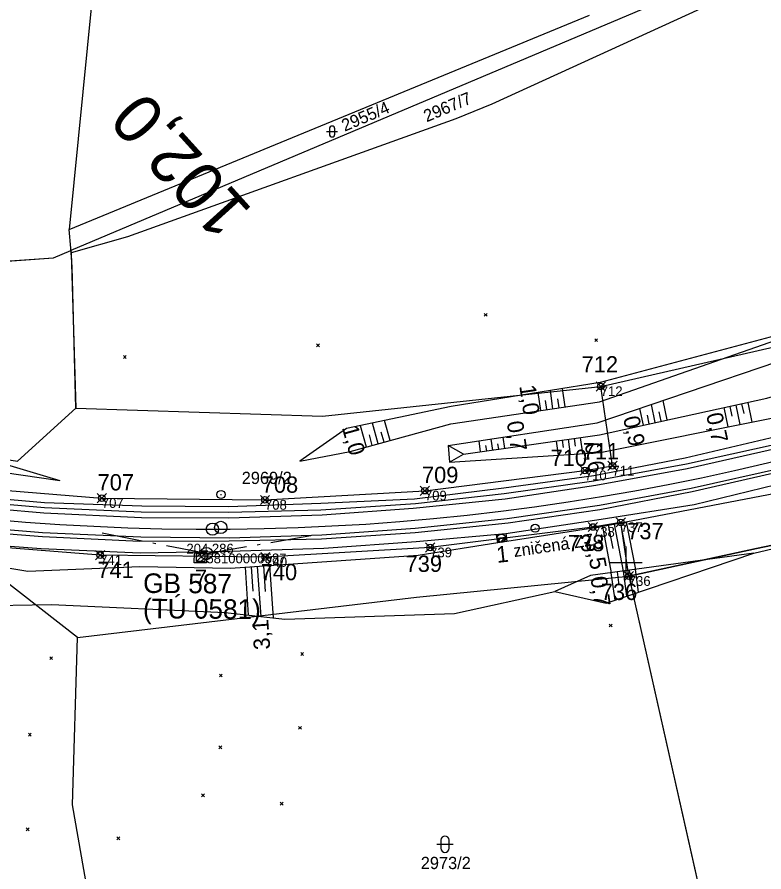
# Model space of a CAD drawing. Extents: x -800194 to -799078, y -1007177 to -1006597.
# Drawn here: x -799674.6 to -799583.1, y -1007037.9 to -1006933.1 of the extents above; entities that cross this region are included whole.
import ezdxf

# ---------------------------------------------------------------- set-up
doc = ezdxf.new("R2010")
doc.units = 0
for name, color, linetype in [('02_Osa_koleje', 7, 'Continuous'), ('_Vrstva 7 - Přesunutá', 7, 'Continuous'), ('Obvod stavby', 7, 'Continuous'), ('Ramove udaje', 7, 'Continuous'), ('Vrstva 11', 7, 'Continuous'), ('Vrstva 12', 7, 'Continuous'), ('Vrstva 4', 7, 'Continuous'), ('Vrstva 48', 7, 'Continuous'), ('Vrstva 49', 7, 'Continuous'), ('Vrstva 50', 7, 'Continuous'), ('Vrstva 53', 7, 'Continuous'), ('Vrstva 55', 7, 'Continuous'), ('Vrstva 57', 7, 'Continuous'), ('Vrstva 58', 7, 'Continuous'), ('Vrstva 60', 7, 'Continuous'), ('Vrstva 61', 7, 'Continuous'), ('Vrstva 63', 7, 'Continuous'), ('Vrstva 7', 7, 'Continuous')]:
    doc.layers.add(name, color=color, linetype=linetype)

msp = doc.modelspace()

# ---------------------------------------------------------------- linework, layer by layer
at = {"layer": '02_Osa_koleje'}
msp.add_arc((-799651.02, -1006703.89), 292, 255.6249, 308.2052, dxfattribs=at)
at = {"layer": '_Vrstva 7 - Přesunutá'}
msp.add_circle((-799650.67, -1006995.89), 0.75, dxfattribs=at)
at = {"layer": 'Obvod stavby'}
for p, q in [((-799603.64, -1006978.96), (-799602.5, -1006977.82)), ((-799603.64, -1006977.82), (-799602.5, -1006978.96)), ((-799605.58, -1006989.27), (-799604.45, -1006988.13)), ((-799605.58, -1006988.13), (-799604.45, -1006989.27)), ((-799602.19, -1006988.7), (-799601.06, -1006987.57)), ((-799602.19, -1006987.57), (-799601.06, -1006988.7)), ((-799625.19, -1006991.75), (-799624.06, -1006990.62)), ((-799625.19, -1006990.62), (-799624.06, -1006991.75)), ((-799664.79, -1006992.66), (-799663.66, -1006991.53)), ((-799664.79, -1006991.53), (-799663.66, -1006992.66)), ((-799644.79, -1006992.88), (-799643.66, -1006991.75)), ((-799644.79, -1006991.75), (-799643.66, -1006992.88)), ((-799601.17, -1006995.62), (-799600.04, -1006994.49)), ((-799601.17, -1006994.49), (-799600.04, -1006995.62)), ((-799604.59, -1006996.19), (-799603.45, -1006995.06)), ((-799604.59, -1006995.06), (-799603.45, -1006996.19)), ((-799624.55, -1006998.72), (-799623.42, -1006997.59)), ((-799624.55, -1006997.59), (-799623.42, -1006998.72)), ((-799664.99, -1006999.65), (-799663.86, -1006998.52)), ((-799664.99, -1006998.52), (-799663.86, -1006999.65)), ((-799644.75, -1006999.88), (-799643.62, -1006998.75)), ((-799644.75, -1006998.75), (-799643.62, -1006999.88)), ((-799600.2, -1007002.22), (-799599.06, -1007001.08)), ((-799600.2, -1007001.08), (-799599.06, -1007002.22))]:
    msp.add_line(p, q, dxfattribs=at)
for points in [[(-799683.81, -1006990.52), (-799664.23, -1006992.09), (-799644.23, -1006992.31), (-799624.62, -1006991.18), (-799605.02, -1006988.7), (-799601.63, -1006988.13), (-799603.07, -1006978.39), (-799559.64, -1006968.48), (-799519.68, -1006952.01)], [(-799521.98, -1006977.8), (-799546.71, -1006987.83), (-799572.22, -1006995.8), (-799583.97, -1006998.26), (-799599.63, -1007001.65), (-799600.6, -1006995.06), (-799604.02, -1006995.63), (-799623.98, -1006998.15), (-799644.19, -1006999.31), (-799664.43, -1006999.09), (-799684.6, -1006997.48)]]:
    msp.add_lwpolyline(points, dxfattribs=at)
for centre in [(-799603.07, -1006978.39), (-799605.02, -1006988.7), (-799601.63, -1006988.13), (-799664.23, -1006992.09), (-799624.62, -1006991.18), (-799644.23, -1006992.31), (-799600.6, -1006995.06), (-799604.02, -1006995.63), (-799623.98, -1006998.15), (-799664.43, -1006999.09), (-799644.19, -1006999.31), (-799599.63, -1007001.65)]:
    msp.add_circle(centre, 0.4, dxfattribs=at)
at = {"layer": 'Ramove udaje'}
for p, q in [((-799600, -1006998), (-799600, -1007002)), ((-799602, -1007000), (-799600, -1007000)), ((-799600, -1007000), (-799598, -1007000))]:
    msp.add_line(p, q, dxfattribs=at)
at = {"layer": 'Vrstva 11'}
for p, q in [((-799614.76, -1006996.92), (-799615.76, -1006997.02)), ((-799615.27, -1006997.47), (-799614.83, -1006996.92)), ((-799615.62, -1006997.31), (-799615.35, -1006996.98)), ((-799652.62, -1006999.86), (-799651.61, -1006998.87)), ((-799652.61, -1006999.33), (-799652.14, -1006998.87)), ((-799652.09, -1006999.87), (-799651.62, -1006999.4))]:
    msp.add_line(p, q, dxfattribs=at)
msp.add_lwpolyline([(-799652.61, -1006998.86), (-799651.61, -1006998.87), (-799651.62, -1006999.87), (-799652.62, -1006999.86)], close=True, dxfattribs=at)
msp.add_circle((-799615.26, -1006996.97), 0.503, dxfattribs=at)
msp.add_arc((-799615.26, -1006996.97), 0.503, 186.0853, 6.0853, dxfattribs=at)
at = {"layer": 'Vrstva 12'}
for points in [[(-799615.84, -1006996.62), (-799614.69, -1006996.42), (-799614.57, -1006997.35), (-799615.7, -1006997.51), (-799615.84, -1006996.62)], [(-799614.69, -1006996.42), (-799614.57, -1006997.35), (-799615.7, -1006997.51), (-799615.84, -1006996.62), (-799614.69, -1006996.42)], [(-799615.84, -1006996.62), (-799615.84, -1006996.62)], [(-799614.69, -1006996.42), (-799614.69, -1006996.42)], [(-799615.7, -1006997.51), (-799615.7, -1006997.51)], [(-799614.57, -1006997.35), (-799614.57, -1006997.35)], [(-799652.9, -1007000.02), (-799652.85, -1006998.81), (-799651.35, -1006998.78), (-799651.4, -1007000.01), (-799652.9, -1007000.02)]]:
    msp.add_lwpolyline(points, dxfattribs=at)
at = {"layer": 'Vrstva 4'}
for points in [[(-799766.32, -1006970.57), (-799760.95, -1006972.54), (-799747.64, -1006977.46), (-799730.55, -1006982.98), (-799710.07, -1006987.58), (-799704.73, -1006988.35), (-799693, -1006990.37), (-799682.43, -1006991.64), (-799671.27, -1006992.62), (-799659.31, -1006993.03), (-799648.69, -1006993.12), (-799637.4, -1006992.7), (-799625.91, -1006992.18), (-799614.96, -1006990.83), (-799603.91, -1006989.31), (-799592.73, -1006987.17), (-799581.6, -1006984.55), (-799570.58, -1006981.6), (-799559.91, -1006978.22), (-799542.96, -1006972.25), (-799531.79, -1006967.66), (-799521.29, -1006962.19), (-799511.24, -1006957.13)], [(-799779.68, -1006964.3), (-799766.32, -1006970.57), (-799761.25, -1006973.18), (-799747.77, -1006978.42), (-799730.77, -1006983.8), (-799710.33, -1006988.71), (-799704.92, -1006989.74), (-799693.13, -1006991.41), (-799682.58, -1006992.93), (-799671.33, -1006993.88), (-799659.36, -1006994.45), (-799648.66, -1006994.5), (-799637.23, -1006994.13), (-799626.07, -1006993.34), (-799614.79, -1006992.17), (-799603.67, -1006990.51), (-799592.47, -1006988.45), (-799581.28, -1006985.92), (-799570.22, -1006983), (-799559.3, -1006979.61), (-799542.38, -1006973.48), (-799531.24, -1006968.77), (-799520.48, -1006963.76), (-799510.39, -1006958.54)], [(-799776.86, -1006969.09), (-799770.96, -1006971.65), (-799761.91, -1006975.65), (-799748.54, -1006980.78), (-799731.46, -1006986.21), (-799711.13, -1006991.05), (-799705.48, -1006992.16), (-799693.53, -1006994.08), (-799682.8, -1006995.38), (-799671.51, -1006996.32), (-799659.45, -1006996.85), (-799648.59, -1006996.95), (-799637.26, -1006996.57), (-799625.83, -1006995.77), (-799614.55, -1006994.59), (-799603.2, -1006992.95), (-799591.97, -1006990.86), (-799580.65, -1006988.34), (-799569.53, -1006985.31), (-799558.56, -1006981.95), (-799541.41, -1006975.74), (-799530.26, -1006971.07), (-799519.46, -1006966), (-799509.25, -1006960.72)], [(-799776.86, -1006969.09), (-799771.26, -1006971.98), (-799762.13, -1006976.09), (-799748.71, -1006981.29), (-799731.51, -1006986.35), (-799711.22, -1006991.46), (-799705.53, -1006992.59), (-799693.58, -1006994.54), (-799682.85, -1006995.9), (-799671.5, -1006996.81), (-799659.56, -1006997.36), (-799648.62, -1006997.34), (-799637.28, -1006997.07), (-799625.83, -1006996.3), (-799614.43, -1006995.11), (-799603.18, -1006993.47), (-799591.85, -1006991.26), (-799580.56, -1006988.7), (-799569.45, -1006985.75), (-799558.39, -1006982.39), (-799541.27, -1006976.23), (-799530.1, -1006971.51), (-799519.4, -1006966.36), (-799509.09, -1006961.13)], [(-799779.01, -1006963.02), (-799770.63, -1006967.94), (-799766.32, -1006970.57), (-799761.02, -1006972.82), (-799747.75, -1006977.97), (-799730.72, -1006983.27), (-799710.2, -1006988.11), (-799704.77, -1006989.18), (-799693.07, -1006990.96), (-799682.55, -1006992.24), (-799671.27, -1006993.22), (-799659.39, -1006993.77), (-799648.66, -1006993.82), (-799637.39, -1006993.53), (-799625.77, -1006992.73), (-799614.9, -1006991.54), (-799603.91, -1006989.96), (-799592.57, -1006987.89), (-799581.42, -1006985.42), (-799570.33, -1006982.33), (-799559.43, -1006979.07), (-799542.6, -1006973.01), (-799531.45, -1006968.25), (-799520.74, -1006963.21)], [(-799683.1, -1006997.41), (-799671.67, -1006998.28), (-799659.52, -1006998.78), (-799648.52, -1006998.59), (-799637.01, -1006998.22), (-799625.7, -1006997.42), (-799614.69, -1006996.42), (-799603.02, -1006994.65), (-799591.63, -1006992.87), (-799579.9, -1006990.02), (-799578.26, -1006989.41), (-799577.13, -1006989.11), (-799569.11, -1006986.79), (-799557.83, -1006983.31), (-799552.61, -1006982.23), (-799552.13, -1006982.09), (-799550.03, -1006981.64), (-799548.93, -1006981.25), (-799540.64, -1006978.12), (-799538.19, -1006977.21), (-799529.22, -1006973.34), (-799517.86, -1006968.17)]]:
    msp.add_lwpolyline(points, dxfattribs=at)
at = {"layer": 'Vrstva 48'}
for p, q in [((-799610.4, -1006981.35), (-799610.72, -1006979.14)), ((-799608.92, -1006981.13), (-799609.24, -1006978.9)), ((-799607.43, -1006980.92), (-799607.76, -1006978.66)), ((-799609.66, -1006981.24), (-799609.82, -1006980.13)), ((-799608.17, -1006981.02), (-799608.34, -1006979.9)), ((-799594.91, -1006982.51), (-799595.43, -1006980.12)), ((-799597.84, -1006983.15), (-799598.29, -1006981.09)), ((-799596.38, -1006982.83), (-799596.86, -1006980.6)), ((-799587.98, -1006981), (-799587.47, -1006983.36)), ((-799587.25, -1006980.84), (-799586.99, -1006982.03)), ((-799586.52, -1006980.68), (-799586, -1006983.07)), ((-799585.79, -1006980.52), (-799585.52, -1006981.72)), ((-799585.05, -1006980.36), (-799584.53, -1006982.77)), ((-799597.11, -1006982.99), (-799597.34, -1006981.92)), ((-799595.64, -1006982.67), (-799595.89, -1006981.52)), ((-799631.79, -1006985.83), (-799632.52, -1006983.21)), ((-799630.35, -1006985.43), (-799631.05, -1006982.9)), ((-799628.9, -1006985.03), (-799629.58, -1006982.59)), ((-799631.07, -1006985.63), (-799631.43, -1006984.34)), ((-799629.63, -1006985.23), (-799629.97, -1006983.99)), ((-799617.8, -1006986.42), (-799617.99, -1006985.08)), ((-799616.31, -1006986.2), (-799616.51, -1006984.85)), ((-799615.57, -1006986.1), (-799615.67, -1006985.42)), ((-799614.83, -1006985.99), (-799615.02, -1006984.62)), ((-799608.55, -1006985.09), (-799608.3, -1006986.83)), ((-799607.81, -1006984.98), (-799607.68, -1006985.88)), ((-799607.07, -1006984.87), (-799606.8, -1006986.73)), ((-799606.33, -1006984.77), (-799606.19, -1006985.72)), ((-799605.59, -1006984.66), (-799605.3, -1006986.63)), ((-799617.05, -1006986.31), (-799617.15, -1006985.64)), ((-799602.87, -1006995.56), (-799601.79, -1007001.23)), ((-799602.14, -1006995.42), (-799601.59, -1006998.27)), ((-799601.4, -1006995.28), (-799600.3, -1007001.03)), ((-799600.66, -1006995.14), (-799600.11, -1006998.03)), ((-799599.93, -1006994.99), (-799598.81, -1007000.83)), ((-799646.67, -1007000.57), (-799646.27, -1007006.43)), ((-799645.93, -1007000.51), (-799645.72, -1007003.51)), ((-799645.18, -1007000.46), (-799644.75, -1007006.6)), ((-799644.43, -1007000.41), (-799644.21, -1007003.55)), ((-799643.68, -1007000.36), (-799643.24, -1007006.78)), ((-799601.07, -1007001.13), (-799600.85, -1007002.75)), ((-799600.33, -1007001.03), (-799599.91, -1007004.12)), ((-799599.58, -1007000.93), (-799599.38, -1007002.41)), ((-799598.84, -1007000.83), (-799598.46, -1007003.63)), ((-799601.81, -1007001.24), (-799601.35, -1007004.61))]:
    msp.add_line(p, q, dxfattribs=at)
at = {"layer": 'Vrstva 49'}
for p, q in [((-799617.34, -1006969.45), (-799616.99, -1006969.8)), ((-799617.34, -1006969.8), (-799616.99, -1006969.45)), ((-799603.8, -1006972.55), (-799603.45, -1006972.9)), ((-799603.8, -1006972.9), (-799603.45, -1006972.55)), ((-799637.9, -1006973.19), (-799637.55, -1006973.54)), ((-799637.9, -1006973.54), (-799637.55, -1006973.19)), ((-799661.58, -1006974.6), (-799661.23, -1006974.96)), ((-799661.58, -1006974.96), (-799661.23, -1006974.6)), ((-799602.04, -1007007.53), (-799601.68, -1007007.88)), ((-799602.04, -1007007.88), (-799601.68, -1007007.53)), ((-799670.61, -1007011.54), (-799670.26, -1007011.89)), ((-799670.61, -1007011.89), (-799670.26, -1007011.54)), ((-799639.85, -1007011.02), (-799639.5, -1007011.38)), ((-799639.85, -1007011.38), (-799639.5, -1007011.02)), ((-799649.82, -1007013.65), (-799649.46, -1007014)), ((-799649.82, -1007014), (-799649.46, -1007013.65)), ((-799673.24, -1007020.91), (-799672.89, -1007021.26)), ((-799673.24, -1007021.26), (-799672.89, -1007020.91)), ((-799640.12, -1007020.07), (-799639.77, -1007020.42)), ((-799640.12, -1007020.42), (-799639.77, -1007020.07)), ((-799649.88, -1007022.46), (-799649.52, -1007022.81)), ((-799649.88, -1007022.81), (-799649.52, -1007022.46)), ((-799652, -1007028.33), (-799651.64, -1007028.69)), ((-799652, -1007028.69), (-799651.64, -1007028.33)), ((-799642.35, -1007029.36), (-799642, -1007029.71)), ((-799642.35, -1007029.71), (-799642, -1007029.36)), ((-799673.5, -1007032.51), (-799673.15, -1007032.86)), ((-799673.5, -1007032.86), (-799673.15, -1007032.51)), ((-799662.38, -1007033.61), (-799662.03, -1007033.96)), ((-799662.38, -1007033.96), (-799662.03, -1007033.61))]:
    msp.add_line(p, q, dxfattribs=at)
for points in [[(-799710.32, -1006994.82), (-799708.87, -1006995.03), (-799692.77, -1006997.82), (-799673.3, -1007001.05), (-799659.56, -1007000.48), (-799648.46, -1007000.69), (-799625.45, -1006999.1), (-799615.7, -1006997.51), (-799614.57, -1006997.35), (-799602.96, -1006995.58), (-799579.5, -1006991.09), (-799558.66, -1006984.76), (-799544.86, -1006980.11), (-799538.19, -1006977.21), (-799529.22, -1006973.34), (-799517.86, -1006968.17), (-799516.56, -1006967), (-799515.53, -1006966.51), (-799507.82, -1006962.78)], [(-799621.79, -1006985.66), (-799603.52, -1006982.85), (-799581.35, -1006975.36), (-799561.47, -1006968.16), (-799550.92, -1006965.64), (-799546.89, -1006968.39)], [(-799619.91, -1006986.72), (-799603.2, -1006984.32), (-799582.71, -1006979.85), (-799558.8, -1006972.84), (-799550.2, -1006969.86), (-799550.92, -1006965.64)], [(-799621.79, -1006985.66), (-799621.59, -1006987.7), (-799603.12, -1006986.49), (-799582.14, -1006982.3), (-799558.67, -1006975.25), (-799547.5, -1006971.75), (-799546.89, -1006968.39)], [(-799641.81, -1007006.94), (-799621, -1007006.24), (-799608.68, -1007003.52), (-799602.42, -1007004.97), (-799584.29, -1006998.85), (-799562.54, -1006993.68), (-799545.4, -1006986.65), (-799532.46, -1006982.15), (-799507.06, -1006970.25)], [(-799574.95, -1006970.38), (-799603.15, -1006977.91), (-799621.41, -1006980.87), (-799634.22, -1006983.56), (-799639.94, -1006987.57)], [(-799639.94, -1006987.57), (-799633.79, -1006986.38), (-799621.45, -1006982.97), (-799603.21, -1006980.3), (-799574.95, -1006970.38)], [(-799728.17, -1006980.61), (-799726.81, -1006975.49), (-799714.47, -1006979.16), (-799704.93, -1006981.25), (-799699.1, -1006983.47), (-799688.78, -1006985.76), (-799678.42, -1006987.22), (-799669.36, -1006989.92)], [(-799728.17, -1006980.61), (-799715.64, -1006982.84), (-799705.85, -1006983.74), (-799700.59, -1006985.51), (-799691.67, -1006987.25), (-799678.69, -1006988.6), (-799669.36, -1006989.92)], [(-799621.59, -1006987.7), (-799619.91, -1006986.72), (-799621.79, -1006985.66)], [(-799716.25, -1006997.26), (-799713.52, -1006997.46), (-799709.9, -1006999.81), (-799706.58, -1006999.54), (-799702.82, -1006999.61), (-799701.05, -1007000.94), (-799691.91, -1007002.76), (-799679.88, -1007005.3), (-799670.42, -1007005.11), (-799649.12, -1007006.1), (-799641.81, -1007006.94)], [(-799584.29, -1006998.85), (-799604.31, -1007001.58), (-799608.68, -1007003.52)]]:
    msp.add_lwpolyline(points, dxfattribs=at)
at = {"layer": 'Vrstva 50'}
msp.add_line((-799611.15, -1006995.79), (-799611.05, -1006995.78), dxfattribs=at)
msp.add_circle((-799611.1, -1006995.78), 0.5, dxfattribs=at)
at = {"layer": 'Vrstva 53'}
for points in [[(-799686.25, -1006963.73), (-799670.17, -1006962.64), (-799668.03, -1006961.74), (-799668, -1006962.02), (-799667.43, -1006981.06), (-799637.16, -1006982.06), (-799603.07, -1006978.39), (-799559.64, -1006968.48), (-799519.68, -1006952.01)], [(-799521.98, -1006977.8), (-799546.71, -1006987.83), (-799572.22, -1006995.8), (-799583.97, -1006998.26), (-799599.63, -1007001.65), (-799584.37, -1007069.36), (-799591.04, -1007071.48), (-799597.25, -1007073.58), (-799607.27, -1007078.7), (-799623.27, -1007096.82), (-799619.94, -1007099.79), (-799606.31, -1007085.7), (-799604.36, -1007100.23), (-799602.09, -1007115.59), (-799604.31, -1007116.28), (-799613.8, -1007119.26), (-799629.52, -1007122.44), (-799580.26, -1007176.65)]]:
    msp.add_lwpolyline(points, dxfattribs=at)
at = {"layer": 'Vrstva 55'}
for p, q in [((-799596.27, -1006931.47), (-799668.03, -1006961.74)), ((-799668.25, -1006959.17), (-799604.43, -1006932.91)), ((-799668, -1006962.02), (-799668.03, -1006961.74)), ((-799599.63, -1007001.65), (-799584.37, -1007069.36))]:
    msp.add_line(p, q, dxfattribs=at)
for points in [[(-799652.26, -1006884.27), (-799656.47, -1006891.91), (-799662.36, -1006908.86), (-799665.44, -1006931.17), (-799668.25, -1006959.17)], [(-799591.61, -1006929.95), (-799590.84, -1006932.11), (-799616.41, -1006943.81), (-799620.83, -1006945.58), (-799661.1, -1006960.05), (-799668, -1006962.02)], [(-799667.43, -1006981.06), (-799637.16, -1006982.06), (-799603.07, -1006978.39), (-799559.64, -1006968.48), (-799519.68, -1006952.01)], [(-799668.03, -1006961.74), (-799668.05, -1006961.46), (-799668.25, -1006959.17)], [(-799599.63, -1007001.65), (-799583.97, -1006998.26), (-799572.22, -1006995.8), (-799546.71, -1006987.83), (-799521.98, -1006977.8), (-799495.25, -1006963.74), (-799489.22, -1006959.79), (-799487.22, -1006958.47)], [(-799686.25, -1006963.73), (-799681.51, -1006963.46), (-799670.17, -1006962.64), (-799668.03, -1006961.74)], [(-799667.43, -1006981.06), (-799667.85, -1006963.74), (-799668, -1006962.02)], [(-799691.32, -1006984.61), (-799685.35, -1006985.87), (-799674.55, -1006987.57), (-799667.43, -1006981.06)], [(-799667.22, -1007009.16), (-799678.94, -1007000.07), (-799720.83, -1006992.39), (-799728.88, -1006993.59), (-799733.28, -1006992.13)], [(-799667.22, -1007009.16), (-799625.65, -1007004.23), (-799599.63, -1007001.65)], [(-799665.73, -1007041.59), (-799667.81, -1007029.7), (-799667.22, -1007009.16)]]:
    msp.add_lwpolyline(points, dxfattribs=at)
at = {"layer": 'Vrstva 58'}
for p, q in [((-799636.67, -1006947.15), (-799635.33, -1006947.15)), ((-799636.33, -1006946.82), (-799636.33, -1006947.49)), ((-799635.67, -1006947.49), (-799635.67, -1006946.82)), ((-799623.16, -1007034.51), (-799621.16, -1007034.51)), ((-799622.66, -1007034.01), (-799622.66, -1007035.01)), ((-799621.66, -1007035.01), (-799621.66, -1007034.01))]:
    msp.add_line(p, q, dxfattribs=at)
for centre, radius, start, end in [((-799636, -1006946.82), 0.335, 0, 180), ((-799636, -1006947.49), 0.335, 180, 359.9879), ((-799622.16, -1007034.01), 0.5, 0, 180), ((-799622.16, -1007035.01), 0.5, 180, 359.9879)]:
    msp.add_arc(centre, radius, start, end, dxfattribs=at)
at = {"layer": 'Vrstva 60'}
for p, q in [((-799603.07, -1006978.39), (-799603.07, -1006978.39)), ((-799601.63, -1006988.13), (-799601.63, -1006988.13)), ((-799605.02, -1006988.7), (-799605.02, -1006988.7)), ((-799624.62, -1006991.18), (-799624.62, -1006991.18)), ((-799664.23, -1006992.09), (-799664.23, -1006992.09)), ((-799644.23, -1006992.31), (-799644.23, -1006992.31)), ((-799604.02, -1006995.63), (-799604.02, -1006995.63)), ((-799600.6, -1006995.06), (-799600.6, -1006995.06)), ((-799651.41, -1006998.88), (-799651.41, -1006998.88)), ((-799623.98, -1006998.15), (-799623.98, -1006998.15)), ((-799664.43, -1006999.09), (-799664.43, -1006999.09)), ((-799644.19, -1006999.31), (-799644.19, -1006999.31)), ((-799599.63, -1007001.65), (-799599.63, -1007001.65))]:
    msp.add_line(p, q, dxfattribs=at)
at = {"layer": 'Vrstva 63'}
for p, q in [((-799659.27, -1006997.35), (-799664.17, -1006996.4)), ((-799643.53, -1006997.51), (-799638.6, -1006996.66)), ((-799657.6, -1006997.68), (-799657.99, -1006997.6)), ((-799651.41, -1006998.88), (-799656.32, -1006997.93)), ((-799645.2, -1006997.8), (-799644.81, -1006997.73)), ((-799651.46, -1006998.88), (-799651.36, -1006998.88)), ((-799651.41, -1006998.88), (-799646.49, -1006998.02))]:
    msp.add_line(p, q, dxfattribs=at)
msp.add_circle((-799651.41, -1006998.88), 0.756, dxfattribs=at)
at = {"layer": 'Vrstva 7'}
msp.add_line((-799649.67, -1006991.64), (-799649.57, -1006991.64), dxfattribs=at)
for centre, radius in [((-799649.62, -1006991.64), 0.5), ((-799649.65, -1006995.68), 0.75)]:
    msp.add_circle(centre, radius, dxfattribs=at)

# ---------------------------------------------------------------- texts
at = {"layer": 'Obvod stavby'}
for s, p in [('712', (-799605.41, -1006976.69)), ('711', (-799605.27, -1006987.33)), ('710', (-799609.21, -1006988.15)), ('709', (-799624.98, -1006990.24)), ('707', (-799664.75, -1006991.15)), ('708', (-799644.62, -1006991.43)), ('737', (-799599.82, -1006997.13)), ('738', (-799607.09, -1006998.6)), ('741', (-799664.77, -1007001.89)), ('739', (-799626.99, -1007001.13)), ('740', (-799644.75, -1007002.15)), ('736', (-799603.06, -1007004.58))]:
    msp.add_text(s, height=2, rotation=360, dxfattribs=at).set_placement(p)
at = {"layer": 'Vrstva 11'}
for s, rotation, p in [('1', 6.0853, (-799615.76, -1007000.03)), ('7', 359.6337, (-799652.82, -1007002.84))]:
    msp.add_text(s, height=2, rotation=rotation, dxfattribs=at).set_placement(p)
at = {"layer": 'Vrstva 48'}
for s, rotation, p in [('1,0', 278.3433, (-799613.05, -1006978.34)), ('0,9', 282.3069, (-799600.34, -1006982.25)), ('0,7', 282.3069, (-799590.16, -1006981.84)), ('1,0', 285.4604, (-799634.81, -1006983.44)), ('0,7', 278.18, (-799614.59, -1006982.76)), ('0,6', 278.18, (-799605.03, -1006985.42)), ('3,5', 280.8184, (-799604.95, -1006997.33)), ('0,7', 277.7544, (-799604.32, -1007001.79)), ('3,1', 93.9585, (-799643.58, -1007010.61))]:
    msp.add_text(s, height=2, rotation=rotation, dxfattribs=at).set_placement(p)
at = {"layer": 'Vrstva 50'}
msp.add_text('zničená ZZ', height=1.5, rotation=8.2838, dxfattribs=at).set_placement((-799613.66, -1006999.32))
at = {"layer": 'Vrstva 57'}
for s, p in [('2967/7', (-799624.4, -1006946.03)), ('2955/4', (-799634.45, -1006947.18))]:
    msp.add_text(s, height=1.5, rotation=23, dxfattribs=at).set_placement(p)
for s, p in [('2969/2', (-799647.08, -1006990.36)), ('2973/2', (-799625.13, -1007037.56))]:
    msp.add_text(s, height=1.5, dxfattribs=at).set_placement(p)
at = {"layer": 'Vrstva 60'}
for s, p in [('712', (-799603.07, -1006979.59)), ('711', (-799601.63, -1006989.33)), ('710', (-799605.02, -1006989.9)), ('709', (-799624.62, -1006992.38)), ('707', (-799664.23, -1006993.29)), ('708', (-799644.23, -1006993.51)), ('738', (-799604.02, -1006996.83)), ('737', (-799600.6, -1006996.26)), ('58100000587', (-799651.41, -1007000.08)), ('739', (-799623.98, -1006999.35)), ('741', (-799664.43, -1007000.29)), ('740', (-799644.19, -1007000.51)), ('736', (-799599.63, -1007002.85))]:
    msp.add_text(s, height=1.2, dxfattribs=at).set_placement(p)
at = {"layer": 'Vrstva 61'}
msp.add_text('204.286', height=1.2, dxfattribs=at).set_placement((-799653.86, -1006998.88))
at = {"layer": 'Vrstva 63'}
for s, p in [('GB 587', (-799659.17, -1007003.71)), ('(TÚ 0581)', (-799659.19, -1007006.82))]:
    msp.add_text(s, height=2.4, rotation=359.6337, dxfattribs=at).set_placement(p)
at = {"layer": 'Vrstva 7'}
msp.add_text('102,0', height=6, rotation=132.1413, dxfattribs=at).set_placement((-799645.63, -1006956.83))

doc.saveas('drawing.dxf')
